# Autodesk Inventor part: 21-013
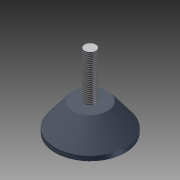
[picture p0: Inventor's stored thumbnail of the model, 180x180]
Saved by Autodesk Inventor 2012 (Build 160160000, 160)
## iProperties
Shininess: 64.0
Length Units: 11269
Angle Units: 11279
Time Units: 11290
Mass Units: 11286
Length Display Precision: 3
Angle Display Precision: 2
Compacted: True
Created: 2003-01
Part Number: 21-013
Vendor: PARKER IPS
Document SubType Name: Modeling
Designer: Autodesk, Inc.
Description: KNUCKLE FOOT 80, M12x80
Catalog Web Link: http://www.parker.com/ead/cm1.asp?cmid=809
Mass: 39.8452 g
Surface Area: 167.331 cm^2
Volume: 39.8452 cm^3
Density: 1 g/cm^3
Material: Default
Density: 0.0
Volumn: 0.0
Area: 0.0
PropertySet Name: Model Information
Control State: 0
Master: False
Checked Out: False
CAGE: 08JJ3
NEXT HIGHER ASSY 01: ---
Author: Autodesk, Inc.
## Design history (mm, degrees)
sketch "Sketch1"
  geometry: L1 (0, 0)-(0, 30); L2 (0, 30)-(19, 30); L3 (19, 30)-(38, 5); L4 (38, 5)-(38, 0); L5 (38, 0)-(0, 0)
  constraints: 10 end point, 2 parallel, 1 perpendicular, 1 vertical, 1 other
  dimensions: "C" = 76 diameter of L4 L1; "d1" = 30 distance of L1.start L1.end (computed from Dmin); "d2" = 5 distance of L3.end L4.end; "d3" = 38 diameter of L2.end L1 (= 0.5 x C)
revolve "Revolution1" sketch "Sketch1" stored, may be unused: angle "d4" = 90 deg
shell "Shell1" dims "d5" = 5
sketch "Sketch2"
  geometry: C1 r 19 at (0, 0) reference; C2 r 6 at (0, 0)
  constraints: 1 centre point, 1 coincident
  dimensions: "d6" = 12 diameter of C2
extrude "Extrusion1" join sketch "Sketch2" distance "d7" = 50 (= Dmax - d1); taper "d8" = 0 deg
thread "Thread1" dims "d9" = 10, "d10" = 0
body "Solid1"
other parameters: "Dmin" = 41 [user parameter; used in 1 equation term], "Dmax" = 80 [user parameter; used in 1 equation term]
